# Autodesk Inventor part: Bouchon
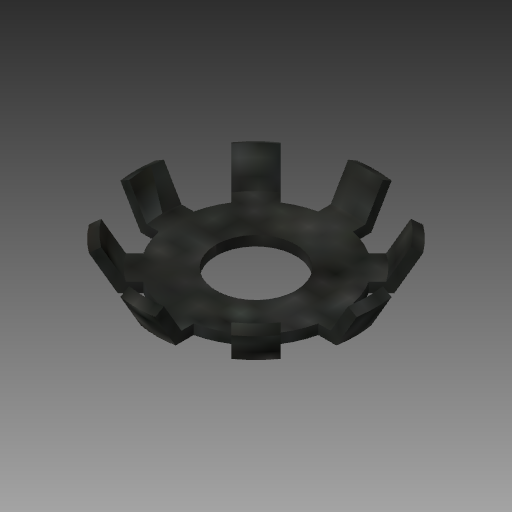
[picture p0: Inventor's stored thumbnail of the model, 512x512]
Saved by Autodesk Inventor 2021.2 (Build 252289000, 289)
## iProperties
Created: 2018-06
Part Number: Bouchon
Material: Acier
Document SubType Name: Modeling
Designer: Fabian Perrée
Density: 7.85 g/cm^3
Appearance: Plaque
Author: Fabian Perrée
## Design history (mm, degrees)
sketch "Esquisse1"
  geometry: L1 (0, 0)-(0, 2); L2 (2, 0)-(4.99, 0); L3 (4.99, 0)-(6, 1.75); L4 (6, 1.75)-(5.567, 2); L5 (5.567, 2)-(4.701, 0.5); L6 (4.701, 0.5)-(2, 0.5); L7 (2, 0.5)-(2, 0)
  constraints: 14 end point, 3 perpendicular, 1 equal length, 1 horizontal, 1 horizontal alignment, 1 parallel, 1 point on line, 1 vertical
  dimensions: "d0" = 4 diameter of L7 L1; "d1" = 60 deg angle of L2 L3; "d2" = 1.75 distance from line of L2 L3.end; "d3" = 12 diameter of L3.end L1; "d4" = 0.5 distance of L3.end L4.end
revolve "Révolution1" sketch "Esquisse1" stored, may be unused: angle "d5" = 90 deg
sketch "Esquisse2"
  geometry: L1 (-6, -0.875)-(-4, -0.875); L2 (-4, -0.875)-(-4, 0.875); L3 (-4, 0.875)-(-6, 0.875); L4 (-6, 0.875)-(-6, -0.875); L5 (-6, 0)-(0, 0); L6 (-3.624, -4.861)-(-2.21, -3.447); L7 (-2.21, -3.447)-(-3.447, -2.21); L8 (-3.447, -2.21)-(-4.861, -3.624); L9 (-4.861, -3.624)-(-3.624, -4.861); L10 (0.875, -6)-(0.875, -4); L11 (0.875, -4)-(-0.875, -4); L12 (-0.875, -4)-(-0.875, -6); L13 (-0.875, -6)-(0.875, -6); L14 (4.861, -3.624)-(3.447, -2.21); L15 (3.447, -2.21)-(2.21, -3.447); L16 (2.21, -3.447)-(3.624, -4.861); L17 (3.624, -4.861)-(4.861, -3.624); L18 (6, 0.875)-(4, 0.875); L19 (4, 0.875)-(4, -0.875); L20 (4, -0.875)-(6, -0.875); L21 (6, -0.875)-(6, 0.875); L22 (3.624, 4.861)-(2.21, 3.447); L23 (2.21, 3.447)-(3.447, 2.21); L24 (3.447, 2.21)-(4.861, 3.624); L25 (4.861, 3.624)-(3.624, 4.861); L26 (-0.875, 6)-(-0.875, 4); L27 (-0.875, 4)-(0.875, 4); L28 (0.875, 4)-(0.875, 6); L29 (0.875, 6)-(-0.875, 6); L30 (-4.861, 3.624)-(-3.447, 2.21); L31 (-3.447, 2.21)-(-2.21, 3.447); L32 (-2.21, 3.447)-(-3.624, 4.861); L33 (-3.624, 4.861)-(-4.861, 3.624); C1 r 2 at (0, 0) reference; A1 r 4.095 centre (0, 0) between (-2.21, -3.447) and (-0.875, -4); A2 r 4.095 centre (0, 0) between (0.875, -4) and (2.21, -3.447); A3 r 4.095 centre (0, 0) between (3.447, -2.21) and (4, -0.875); A4 r 4.095 centre (0, 0) between (4, 0.875) and (3.447, 2.21); A5 r 4.095 centre (0, 0) between (2.21, 3.447) and (0.875, 4); A6 r 4.095 centre (0, 0) between (-0.875, 4) and (-2.21, 3.447); A7 r 4.095 centre (0, 0) between (-3.447, 2.21) and (-4, 0.875); A8 r 4.095 centre (0, 0) between (-4, -0.875) and (-3.447, -2.21); 7 further points
  constraints: 66 end point, 16 point on circle, 8 centre point, 8 midpoint, 2 parallel, 2 perpendicular, 1 coincident, 1 horizontal, 1 horizontal alignment, 1 vertical, 75 other
  dimensions: "d6" = 1.75 distance of L3.end L1.start; "d7" = 4 distance from line of C1.centre L2; "d10" = 360 deg dimension on C1.centre L1.start (derived)
extrude "Extrusion1" sketch "Esquisse2" extent not by distance; stored distance "d12" = 0; taper "d13" = 0 deg
node "Solide1"
